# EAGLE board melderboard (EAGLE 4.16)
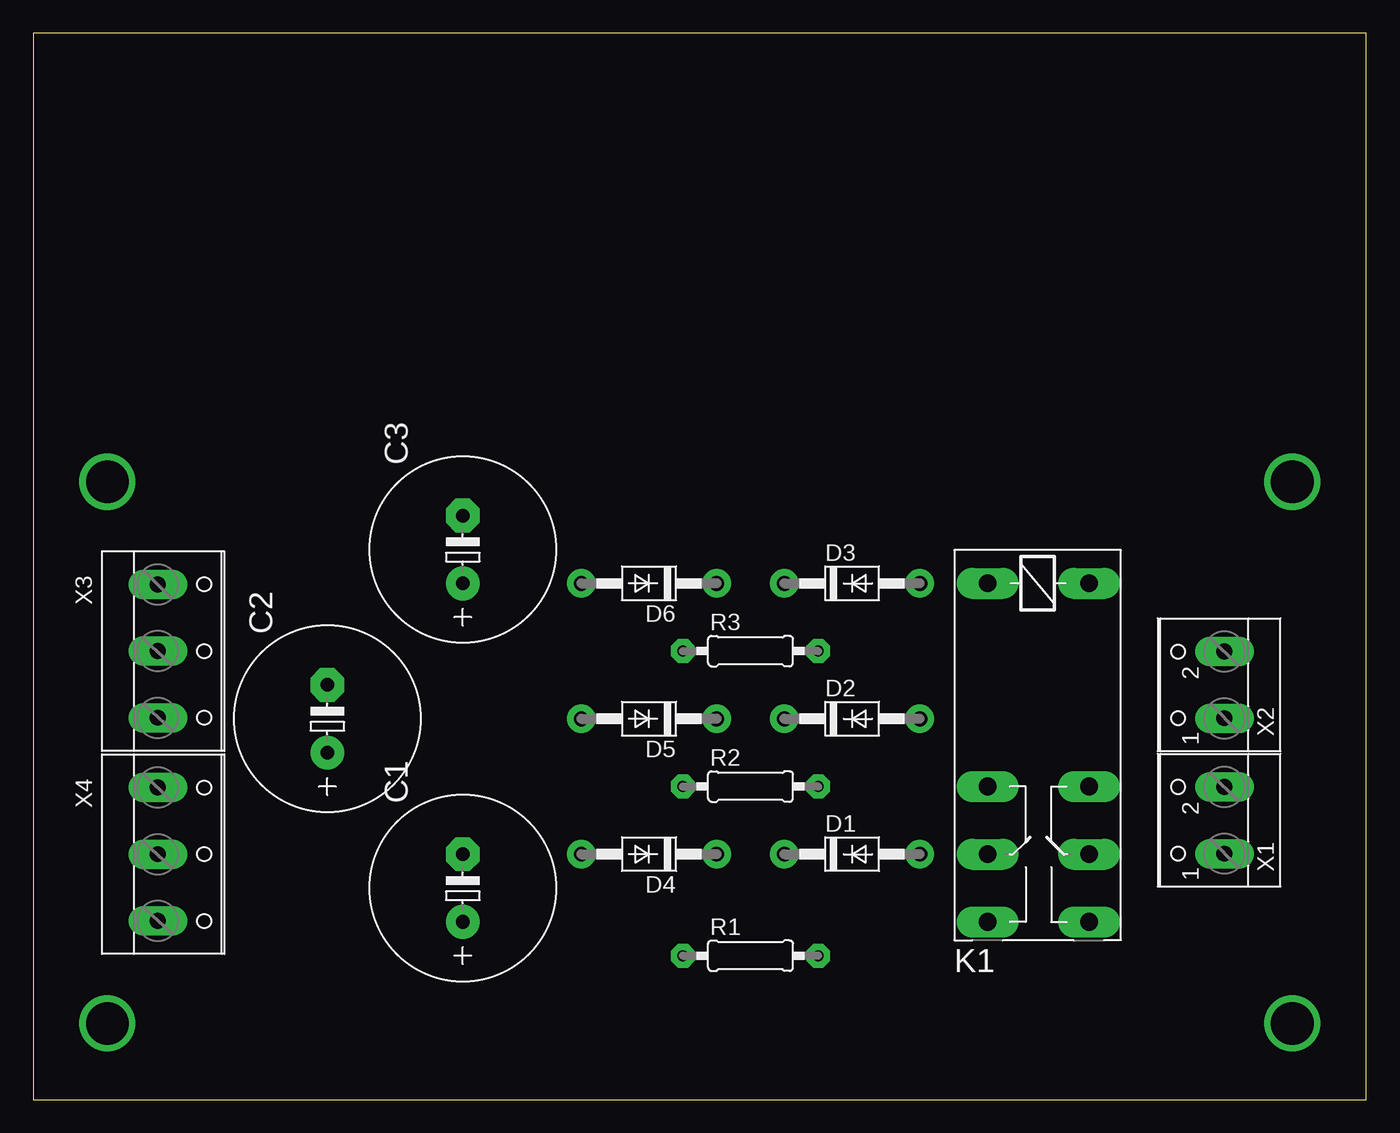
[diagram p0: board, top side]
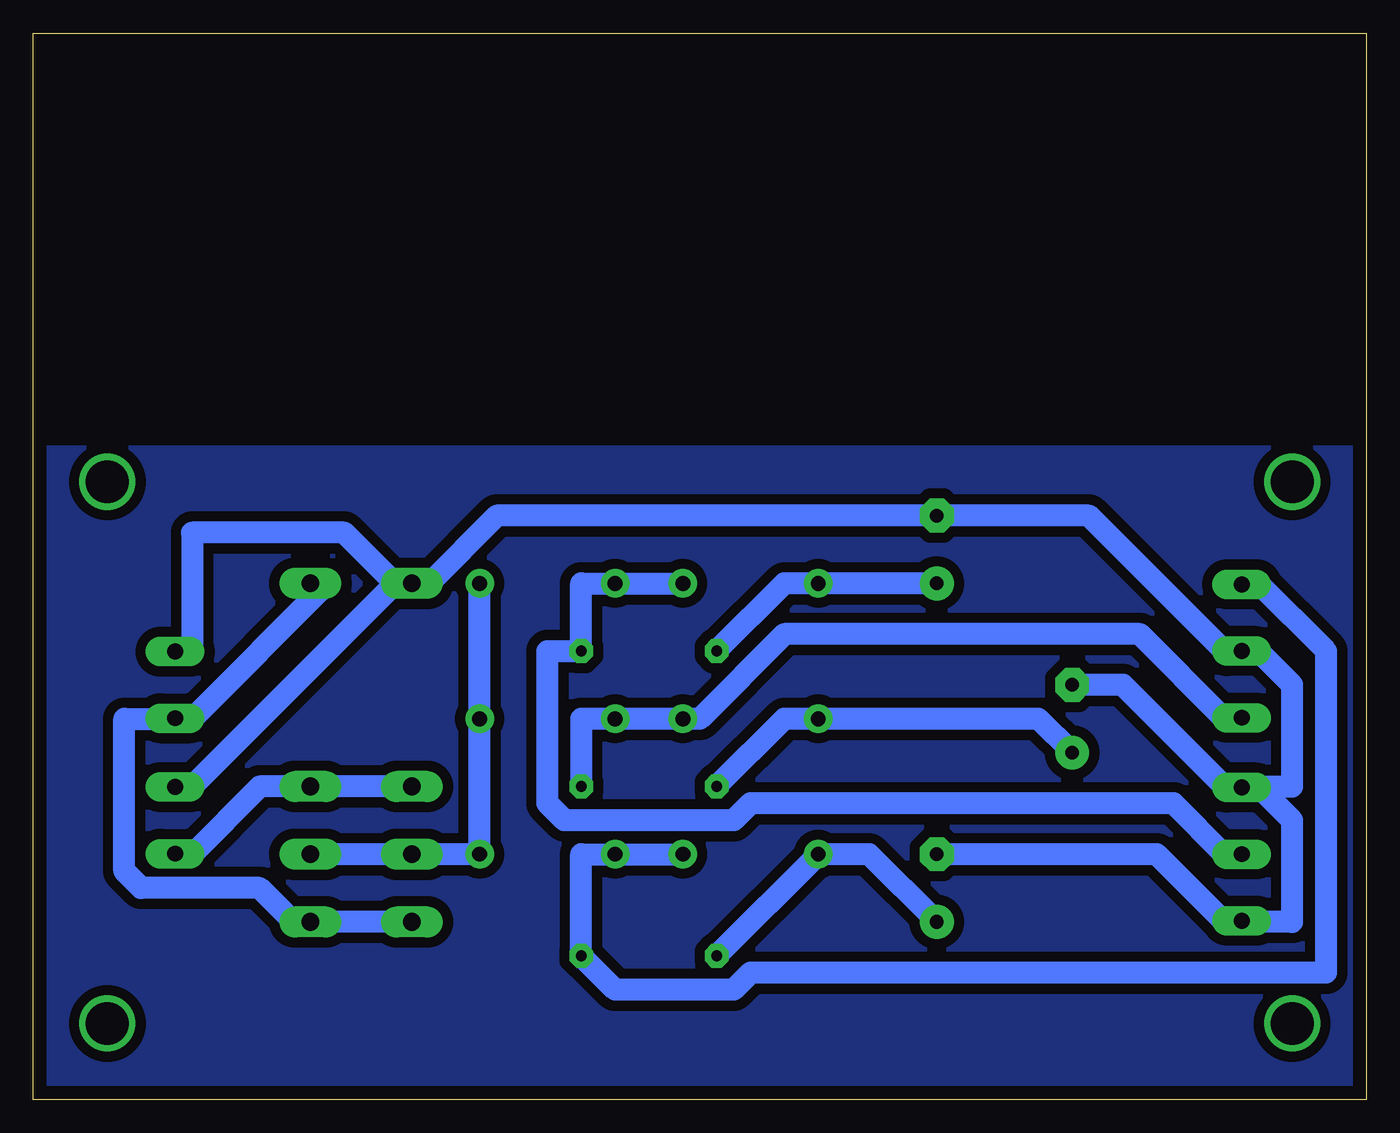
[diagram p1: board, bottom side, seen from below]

Size 100 x 80 mm. Coordinates in mm from the lower left corner, seen from the top.
Outline: 0,0 100,0 100,80 0,80 0,0
Copper layers (1*16): Top 0.035mm / dielectric 1.5mm / Bottom 0.035mm
Design rules "netzboard": minimum track width 65mil, minimum drill 24mil, track to track 30mil, track to pad 30mil, pad to pad 30mil, via to via 8mil, smd to smd 8mil, copper to edge 40mil, drill to drill 8mil, minimum pad ring 10mil, minimum via ring 8mil, stop-mask expansion 4mil, vias tented up to drill 0mil, thermal gap 10mil

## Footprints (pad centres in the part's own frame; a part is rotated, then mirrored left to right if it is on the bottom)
E5-13 = drill 1.016 pad 2.54 round: + -2.54,0 | drill 1.016 pad 2.54 octagon: - 2.54,0
DO41-10 = drill 1.118 round: A 5.08,0; C -5.08,0
RP420 = drill 1.321 long: 11 16.51,-3.81; 12 11.43,-3.81; 14 21.59,-3.81; 21 16.51,3.81; 22 11.43,3.81; 24 21.59,3.81; A1 -3.81,-3.81; A2 -3.81,3.81
0207/10 = drill 0.813 octagon: 1 -5.08,0; 2 5.08,0
W237-102 = drill 1.194 long: 1 -2.5,-1.27; 2 2.5,-1.27
W237-103 = drill 1.194 long: 1 -5,-1.29; 2 0,-1.29; 3 5,-1.29

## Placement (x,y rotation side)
C1  [E5-13]  32.22,15.87 90 top
C2  [E5-13]  22.06,28.57 90 top
C3  [E5-13]  32.22,41.27 90 top
D1  1N4004  [DO41-10]  61.43,18.41 0 top
D2  1N4004  [DO41-10]  61.43,28.57 0 top
D3  1N4004  [DO41-10]  61.43,38.73 0 top
D4  1N4004  [DO41-10]  46.19,18.41 180 top
D5  1N4004  [DO41-10]  46.19,28.57 180 top
D6  1N4004  [DO41-10]  46.19,38.73 180 top
K1  RP420024  [RP420]  75.4,34.92 270 top
R1  [0207/10]  53.81,10.79 0 top
R2  [0207/10]  53.81,23.49 0 top
R3  [0207/10]  53.81,33.65 0 top
X1  [W237-102]  88.1,20.95 90 top
X2  [W237-102]  88.1,31.11 90 top
X3  [W237-103]  10.63,33.65 270 top
X4  [W237-103]  10.63,18.41 270 top

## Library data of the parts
C1-C3 R1-R3 = rcl
D1-D6 = diode
K1 = relay
X1-X4 = con-wago-500

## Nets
N$1: D1.A D2.A D3.A K1.11 K1.21
N$2: D1.C D4.C R1.2 X3.1
N$3: D2.C D5.C R2.2 X3.3
N$4: D3.C D6.C R3.2 X4.2
N$7: C1.+ D4.A R1.1
N$8: C2.+ D5.A R2.1
N$9: C3.+ D6.A R3.1
N$12: K1.12 K1.22 X1.1
N$14: K1.14 K1.24 K1.A2 X2.1
N$16: C1.- C2.- C3.- K1.A1 X1.2 X2.2 X3.2 X4.1 X4.3

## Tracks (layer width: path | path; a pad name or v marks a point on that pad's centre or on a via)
N$1
  Bottom 1.651: D3.A D2.A D1.A K1.11 K1.21
N$2
  Bottom 1.651: D4.C D1.C 58.89,18.41 R1.2 56.35,8.25 47.46,8.25 46.19,9.52 3.01,9.52 3.01,33.65 8.09,38.73 X3.1
N$3
  Bottom 1.651: R2.2 58.89,28.57 D2.C D5.C 50,28.57 43.65,34.92 16.98,34.92 10.63,28.57 X3.3
N$4
  Bottom 1.651: D6.C D3.C 58.89,38.73 R3.2 61.43,33.65 61.43,22.22 60.16,20.95 47.46,20.95 46.19,22.22 14.44,22.22 10.63,18.41 X4.2
N$5  (via drill 3.2)
  other vias: 5.55,5.71
N$6  (via drill 3.2)
  other vias: 94.45,5.71
N$7
  Bottom 1.651: R1.1 D4.A 37.3,18.41 C1.+
N$8
  Bottom 1.651: R2.1 43.65,28.57 D5.A 24.6,28.57 C2.+
N$9
  Bottom 1.651: R3.1 43.65,38.73 D6.A C3.+
N$10  (via drill 3.2)
  other vias: 5.55,46.35
N$11  (via drill 3.2)
  other vias: 94.45,46.35
N$12
  Bottom 1.651: X1.1 88.1,18.41 83.02,23.49 K1.22 K1.12
N$13
  pour Bottom: 0.47,48.89 99.53,48.89 99.53,0.63 0.47,0.63
N$14
  Bottom 1.651: K1.14 K1.24 80.48,13.33 83.02,15.87 91.91,15.87 93.18,17.14 93.18,28.57 90.64,28.57 X2.1 88.1,28.57 77.94,38.73 K1.A2
N$16
  Bottom 1.651: 72.86,38.73 88.1,23.49 X1.2 | 72.86,38.73 76.67,42.54 88.1,42.54 88.1,33.65 X2.2 | 72.86,38.73 K1.A1 70.32,38.73 65.24,43.81 C3.- 20.79,43.81 10.63,33.65 X3.2 8.09,33.65 5.55,31.11 5.55,23.49 8.09,23.49 | C2.- 18.25,31.11 10.63,23.49 X4.1 8.09,23.49 | C1.- 15.71,18.41 10.63,13.33 X4.3 8.09,13.33 5.55,13.33 5.55,20.95 8.09,23.49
